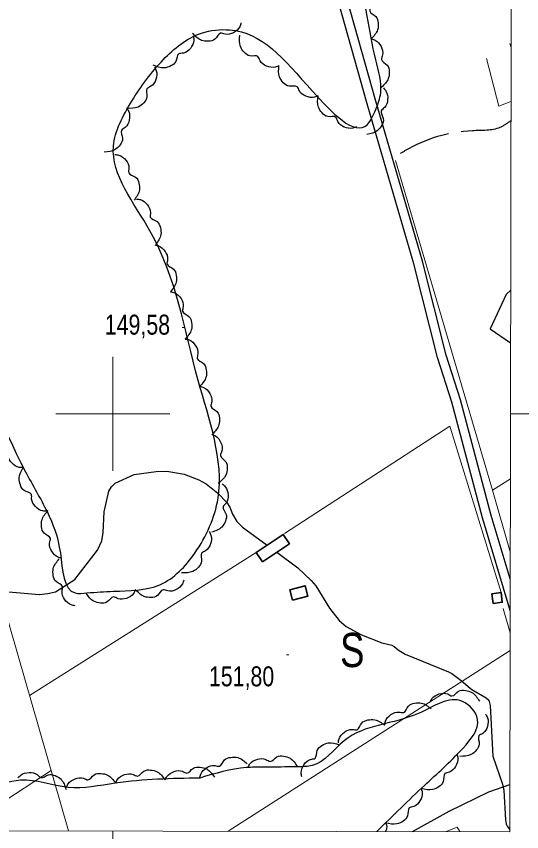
# Model space of a CAD drawing. Extents: x 483843 to 488449, y 4381269 to 4384483.
# Drawn here: x 487457.6 to 487679.3, y 4381816.7 to 4382174.3 of the extents above; entities that cross this region are included whole.
import ezdxf
from ezdxf.enums import TextEntityAlignment as Align

# ---------------------------------------------------------------- set-up
doc = ezdxf.new("R2010")
doc.units = 0
doc.header["$LTSCALE"] = 3.8
doc.linetypes.add('LONG_DASHED', pattern=[7.5, 6, -1.5])
for name, color, linetype, lineweight in [('1', 7, 'Continuous', 13), ('25', 7, 'LONG_DASHED', 25), ('27', 7, 'Continuous', 25), ('38', 7, 'Continuous', 25), ('47', 7, 'Continuous', 35), ('51', 7, 'Continuous', 13), ('7', 7, 'Continuous', 13), ('8', 7, 'Continuous', 25)]:
    doc.layers.add(name, color=color, linetype=linetype, lineweight=lineweight)
doc.layers.add('31', color=7, linetype='Continuous')

msp = doc.modelspace()

# ---------------------------------------------------------------- linework, layer by layer
at = {"layer": '1'}
for p, q in [((487500, 4382025), (487500, 4381975)), ((487475, 4382000), (487525, 4382000)), ((487674.41, 4382000), (487744.45, 4382000)), ((487500, 4381817.04), (487500, 4381745.69))]:
    msp.add_line(p, q, dxfattribs=at)
msp.add_lwpolyline([(484100.5, 4384135.8), (487678, 4384129), (487674.1, 4381816.7), (484095.6, 4381823.6)], close=True, dxfattribs=at)
at = {"layer": '25'}
for points in [[(487674.5, 4382054.12), (487672.47, 4382052.25), (487665.51, 4382037.18), (487674.46, 4382031.09)], [(487631.49, 4381816.78), (487647.5, 4381825.67), (487664.88, 4381834.13), (487674.14, 4381837.47)]]:
    msp.add_lwpolyline(points, dxfattribs=at)
at = {"layer": '27'}
for points in [[(486286.37, 4382818.73), (486339.99, 4382829.8), (486391.37, 4382851.5), (486440.09, 4382863.84), (486483.65, 4382864.6), (486530.94, 4382876.91), (486556.13, 4382891.91), (486581.09, 4382903.76), (486654.31, 4382924.49), (486662.47, 4382925.04), (486711.17, 4382931.08), (486727.4, 4382937.04), (486766.91, 4382937.87), (486808.31, 4382909.18), (486821.81, 4382880.51), (486820.67, 4382841.64), (486812.49, 4382812.89), (486799.42, 4382770.69), (486791.78, 4382745.03), (486785, 4382714.29), (486784.58, 4382691.25), (486792.33, 4382675.66), (486812.73, 4382668.89), (486834.8, 4382649.92), (486842.09, 4382627.43), (486847.24, 4382607.13), (486841.07, 4382582.93), (486840.3, 4382544.36), (486820.33, 4382480.87), (486817.63, 4382459.06), (486815.97, 4382420.47), (486812.52, 4382387.85), (486799.99, 4382362.84), (486771.04, 4382337.85), (486733.51, 4382314.2), (486712.72, 4382296.59), (486687.38, 4382263.88), (486690.96, 4382229.15), (486713.22, 4382200.82), (486764.33, 4382192.43), (486778.5, 4382149.68), (486779.01, 4382117.89), (486787.15, 4382072.98), (486813.93, 4382065.66), (486857.54, 4382071.08), (486866.35, 4382080.34), (486893.23, 4382096.95), (486915.85, 4382116.25), (486928.06, 4382127.9), (486936.43, 4382157.7), (486928.1, 4382176.05), (486914.22, 4382205.24), (486902.98, 4382218.81), (486885.61, 4382249.79), (486879.29, 4382279.36), (486884.99, 4382315.26), (486888.52, 4382343.76), (486907.35, 4382375.88), (486922.54, 4382388.35), (486945.58, 4382366.33), (486954.28, 4382323.31), (486963.51, 4382283.6), (486982.52, 4382253.24), (487009.26, 4382225.98), (487037.6, 4382230.32), (487058.96, 4382252.37), (487069.68, 4382284.84), (487065.95, 4382338.17), (487054.24, 4382363.72), (487038.01, 4382386.56), (487027.59, 4382400.37), (487012.06, 4382422.24), (486991.9, 4382450.1), (486977.88, 4382471.56), (486976.21, 4382486.9), (486980.43, 4382521.64), (487024.88, 4382562.69), (487055.81, 4382565.06), (487106.74, 4382596.8), (487155.96, 4382614.11), (487207.74, 4382666.72), (487232.21, 4382676.6), (487267.31, 4382683.94), (487282.71, 4382693.48), (487294.56, 4382707.98), (487340.16, 4382736.84), (487389.67, 4382736.07), (487421.36, 4382716.33), (487454.29, 4382680.57), (487455.44, 4382629.06), (487501.37, 4382598.97)], [(487674.99, 4382327.12), (487600.73, 4382281.96), (487559.96, 4382263.02), (487543.94, 4382264.48), (487524.28, 4382275.4), (487514.82, 4382289.97), (487514.82, 4382303.08), (487510.45, 4382314.01), (487500.26, 4382321.29), (487492.98, 4382322.75), (487481.33, 4382316.2), (487455.84, 4382279.05), (487420.9, 4382255.74), (487361.2, 4382229.51), (487353.92, 4382233.16), (487333.53, 4382276.86), (487330.62, 4382282.69), (487326.25, 4382284.15), (487321.15, 4382280.5), (487262.18, 4382225.87), (487217.04, 4382194.55), (487186.46, 4382174.88), (487179.18, 4382164.69), (487185.01, 4382145.02), (487193.01, 4382101.31), (487202.48, 4382091.85), (487210.49, 4382084.56), (487220.68, 4382080.92), (487233.79, 4382087.47), (487262.91, 4382104.96), (487326.98, 4382145.75), (487337.9, 4382147.93), (487343, 4382145.02), (487345.91, 4382133.36), (487351.73, 4382112.24), (487364.11, 4382095.49), (487370.66, 4382086.75), (487375.76, 4382079.46), (487377.94, 4382072.18), (487375.76, 4382064.89), (487372.12, 4382058.34), (487375.03, 4382046.68), (487383.77, 4382031.39), (487391.05, 4382027.75), (487408.52, 4382034.3), (487418.71, 4382042.31), (487424.54, 4382039.4), (487429.63, 4382034.3), (487461.67, 4381974.57), (487471.13, 4381957.09), (487476.96, 4381938.88), (487483.51, 4381921.4), (487488.61, 4381921.4), (487500.26, 4381922.13), (487520.64, 4381925.04), (487535.93, 4381938.88), (487546.12, 4381962.92), (487537.39, 4382014.63), (487516.27, 4382080.19), (487500.26, 4382117.34), (487508.26, 4382137.01), (487522.1, 4382155.22), (487538.84, 4382166.87), (487551.22, 4382168.33), (487587.62, 4382141.38), (487611.65, 4382126.81), (487615.29, 4382133.36), (487617.47, 4382140.65), (487615.29, 4382155.22), (487605.83, 4382193.09), (487591.99, 4382228.79), (487597.09, 4382238.26), (487616.75, 4382255.01), (487651.69, 4382276.86), (487675.72, 4382292.16)], [(487607.84, 4382185.35), (487609.55, 4382184.86), (487612.24, 4382182.19), (487613.06, 4382178.59), (487612.69, 4382176.57), (487615.34, 4382174.2), (487616.38, 4382171.4), (487616.15, 4382168.39), (487613.28, 4382164.34)], [(487556.19, 4382171.36), (487555.64, 4382169.67), (487552.88, 4382167.07), (487549.25, 4382166.38), (487547.25, 4382166.83), (487544.78, 4382164.27), (487541.95, 4382163.34), (487538.94, 4382163.68), (487535, 4382166.69)], [(487572.85, 4382152.64), (487571.2, 4382151.98), (487567.44, 4382152.45), (487564.59, 4382154.8), (487563.66, 4382156.63), (487560.11, 4382156.89), (487557.58, 4382158.48), (487555.92, 4382161.01), (487555.72, 4382165.96)], [(487535.36, 4382165.44), (487535.51, 4382163.67), (487533.98, 4382160.2), (487530.91, 4382158.15), (487528.89, 4382157.78), (487527.62, 4382154.46), (487525.37, 4382152.5), (487522.47, 4382151.64), (487517.67, 4382152.87)], [(487613.42, 4382164.38), (487615.1, 4382163.8), (487617.65, 4382160.99), (487618.28, 4382157.36), (487617.8, 4382155.36), (487620.32, 4382152.85), (487621.21, 4382150), (487620.82, 4382147), (487617.75, 4382143.11)], [(487518.26, 4382151.96), (487519.03, 4382150.37), (487518.83, 4382146.58), (487516.69, 4382143.57), (487514.93, 4382142.51), (487514.93, 4382138.95), (487513.52, 4382136.32), (487511.12, 4382134.49), (487506.19, 4382133.93)], [(487590.1, 4382139.49), (487588.46, 4382138.82), (487584.69, 4382139.25), (487581.82, 4382141.57), (487580.87, 4382143.39), (487577.32, 4382143.61), (487574.77, 4382145.17), (487573.09, 4382147.69), (487572.84, 4382152.64)], [(487618.64, 4382142.84), (487619.79, 4382141.48), (487620.53, 4382137.76), (487619.19, 4382134.32), (487617.75, 4382132.85), (487618.62, 4382129.4), (487617.91, 4382126.5), (487616.03, 4382124.14), (487611.39, 4382122.38)], [(487606.94, 4382125.82), (487605.28, 4382125.19), (487601.52, 4382125.72), (487598.72, 4382128.12), (487597.82, 4382129.97), (487594.28, 4382130.29), (487591.77, 4382131.92), (487590.16, 4382134.48), (487590.05, 4382139.44)], [(487505.98, 4382134.06), (487506.94, 4382132.57), (487507.21, 4382128.78), (487505.46, 4382125.53), (487503.84, 4382124.26), (487504.27, 4382120.73), (487503.21, 4382117.94), (487501.05, 4382115.83), (487496.23, 4382114.67)], [(487500.86, 4382113.64), (487502.62, 4382113.42), (487505.69, 4382111.19), (487507.04, 4382107.76), (487506.98, 4382105.7), (487509.95, 4382103.76), (487511.4, 4382101.15), (487511.63, 4382098.14), (487509.41, 4382093.7)], [(487510.31, 4382094.13), (487512.07, 4382093.91), (487515.14, 4382091.67), (487516.49, 4382088.23), (487516.42, 4382086.18), (487519.39, 4382084.23), (487520.83, 4382081.62), (487521.06, 4382078.61), (487518.83, 4382074.17)], [(487518.34, 4382074), (487520.08, 4382073.63), (487522.95, 4382071.15), (487524.01, 4382067.62), (487523.78, 4382065.58), (487526.59, 4382063.4), (487527.81, 4382060.67), (487527.79, 4382057.65), (487525.21, 4382053.41)], [(487525.34, 4382053.47), (487527.07, 4382053.06), (487529.89, 4382050.52), (487530.87, 4382046.97), (487530.59, 4382044.93), (487533.35, 4382042.69), (487534.52, 4382039.94), (487534.43, 4382036.92), (487531.76, 4382032.74)], [(487531.77, 4382032.75), (487533.49, 4382032.35), (487536.31, 4382029.81), (487537.3, 4382026.25), (487537.02, 4382024.22), (487539.78, 4382021.97), (487540.95, 4382019.22), (487540.86, 4382016.2), (487538.19, 4382012.02)], [(487538.09, 4382012.01), (487539.8, 4382011.53), (487542.52, 4382008.88), (487543.37, 4382005.29), (487543.01, 4382003.27), (487545.67, 4382000.92), (487546.73, 4381998.13), (487546.52, 4381995.11), (487543.69, 4381991.04)], [(487460.71, 4381976.37), (487458.93, 4381976.44), (487455.68, 4381978.4), (487454.04, 4381981.7), (487453.93, 4381983.75), (487450.79, 4381985.43), (487449.12, 4381987.91), (487448.64, 4381990.89), (487450.47, 4381995.5)], [(487543.44, 4381990.97), (487545.07, 4381990.27), (487547.42, 4381987.29), (487547.78, 4381983.62), (487547.16, 4381981.66), (487549.5, 4381978.98), (487550.18, 4381976.07), (487549.57, 4381973.11), (487546.23, 4381969.45)], [(487471.07, 4381957.32), (487469.3, 4381957.37), (487466.04, 4381959.31), (487464.37, 4381962.6), (487464.24, 4381964.65), (487461.09, 4381966.31), (487459.41, 4381968.77), (487458.9, 4381971.75), (487460.7, 4381976.37)], [(487548, 4381969.21), (487549.3, 4381968), (487550.51, 4381964.41), (487549.63, 4381960.82), (487548.38, 4381959.19), (487549.68, 4381955.88), (487549.35, 4381952.91), (487547.79, 4381950.33), (487543.41, 4381948)], [(487477.67, 4381936.68), (487475.95, 4381937.11), (487473.18, 4381939.7), (487472.26, 4381943.28), (487472.57, 4381945.3), (487469.85, 4381947.6), (487468.73, 4381950.36), (487468.88, 4381953.38), (487471.62, 4381957.52)], [(487542.26, 4381948.3), (487543.03, 4381946.7), (487542.82, 4381942.91), (487540.67, 4381939.91), (487538.91, 4381938.85), (487538.89, 4381935.29), (487537.49, 4381932.66), (487535.08, 4381930.84), (487530.15, 4381930.29)], [(487483.44, 4381915.83), (487481.7, 4381916.18), (487478.81, 4381918.64), (487477.71, 4381922.16), (487477.93, 4381924.21), (487475.11, 4381926.37), (487473.86, 4381929.08), (487473.86, 4381932.1), (487476.41, 4381936.36)], [(487531.14, 4381927.07), (487530.55, 4381925.4), (487527.72, 4381922.87), (487524.07, 4381922.28), (487522.08, 4381922.78), (487519.55, 4381920.29), (487516.69, 4381919.43), (487513.7, 4381919.85), (487509.83, 4381922.96)], [(487509.86, 4381922.76), (487509.06, 4381921.18), (487505.93, 4381919.03), (487502.25, 4381918.89), (487500.33, 4381919.64), (487497.51, 4381917.48), (487494.56, 4381916.98), (487491.65, 4381917.77), (487488.2, 4381921.34)], [(487615.72, 4381816.81), (487636.69, 4381836.99), (487653.6, 4381853.4), (487660.01, 4381865.98), (487653.32, 4381873.87), (487634.38, 4381868.74), (487601.4, 4381856.58), (487587.46, 4381845.71), (487581.32, 4381845.21), (487578.69, 4381845.16), (487565.72, 4381845.03), (487558.6, 4381844.81), (487538.14, 4381840.26)], [(487639.11, 4381873.57), (487639.97, 4381875.12), (487643.19, 4381877.13), (487646.88, 4381877.1), (487648.76, 4381876.27), (487651.68, 4381878.3), (487654.64, 4381878.66), (487657.52, 4381877.74), (487660.8, 4381874.02)], [(487619.2, 4381863.4), (487619.54, 4381865.14), (487621.97, 4381868.05), (487625.49, 4381869.17), (487627.53, 4381868.97), (487629.67, 4381871.81), (487632.37, 4381873.08), (487635.4, 4381873.11), (487639.67, 4381870.59)], [(487598.94, 4381855.63), (487599.23, 4381857.38), (487601.57, 4381860.37), (487605.05, 4381861.59), (487607.1, 4381861.45), (487609.15, 4381864.35), (487611.82, 4381865.7), (487614.84, 4381865.82), (487619.19, 4381863.43)], [(487663.5, 4381868.28), (487664.33, 4381866.71), (487664.29, 4381862.92), (487662.27, 4381859.83), (487660.56, 4381858.69), (487660.7, 4381855.14), (487659.41, 4381852.45), (487657.08, 4381850.52), (487652.18, 4381849.76)], [(487582.92, 4381840.74), (487582.61, 4381842.49), (487583.82, 4381846.08), (487586.7, 4381848.4), (487588.67, 4381848.95), (487589.64, 4381852.37), (487591.7, 4381854.53), (487594.51, 4381855.65), (487599.4, 4381854.86)], [(487538.14, 4381840.26), (487538.56, 4381841.98), (487541.12, 4381844.78), (487544.69, 4381845.74), (487546.72, 4381845.44), (487548.99, 4381848.18), (487551.75, 4381849.32), (487554.77, 4381849.21), (487558.92, 4381846.5)], [(487559.27, 4381844.97), (487560.15, 4381846.51), (487563.4, 4381848.48), (487567.09, 4381848.4), (487568.95, 4381847.55), (487571.9, 4381849.55), (487574.86, 4381849.88), (487577.73, 4381848.93), (487580.97, 4381845.17)], [(487650.91, 4381850.73), (487651.32, 4381849.01), (487650.33, 4381845.35), (487647.6, 4381842.86), (487645.66, 4381842.2), (487644.9, 4381838.72), (487642.97, 4381836.44), (487640.23, 4381835.16), (487635.3, 4381835.66)], [(487501.24, 4381837.99), (487502.04, 4381839.58), (487505.17, 4381841.73), (487508.86, 4381841.86), (487510.77, 4381841.12), (487513.59, 4381843.28), (487516.54, 4381843.77), (487519.45, 4381842.99), (487522.9, 4381839.41)], [(487522.9, 4381839.39), (487523.71, 4381840.97), (487526.86, 4381843.09), (487530.55, 4381843.19), (487532.45, 4381842.43), (487535.3, 4381844.57), (487538.24, 4381845.03), (487541.15, 4381844.22), (487544.56, 4381840.62)], [(487538.14, 4381840.26), (487501.06, 4381837.98), (487480.33, 4381836.13), (487459.41, 4381839.29), (487445.42, 4381833.82), (487434.09, 4381817.16)], [(487458.38, 4381840.28), (487459.61, 4381841.56), (487463.23, 4381842.69), (487466.79, 4381841.73), (487468.4, 4381840.46), (487471.74, 4381841.69), (487474.7, 4381841.3), (487477.25, 4381839.69), (487479.49, 4381835.26)], [(487479.63, 4381836.07), (487480.39, 4381837.67), (487483.45, 4381839.9), (487487.14, 4381840.13), (487489.07, 4381839.44), (487491.84, 4381841.67), (487494.77, 4381842.24), (487497.7, 4381841.53), (487501.24, 4381838.05)], [(487635.3, 4381835.66), (487635.72, 4381833.93), (487634.71, 4381830.27), (487631.98, 4381827.79), (487630.04, 4381827.13), (487629.27, 4381823.66), (487627.34, 4381821.38), (487624.6, 4381820.1), (487619.66, 4381820.61)], [(487619.75, 4381820.52), (487620.14, 4381818.79), (487619.57, 4381816.81)]]:
    msp.add_spline(points, degree=3, dxfattribs=at)
at = {"layer": '38'}
for p, q in [((487674.26, 4381913.65), (487674.26, 4381913.66)), ((487674.26, 4381913.64), (487674.26, 4381913.65)), ((487674.26, 4381913.63), (487674.26, 4381913.64)), ((487674.26, 4381913.62), (487674.26, 4381913.63)), ((487674.26, 4381913.61), (487674.26, 4381913.62)), ((487674.26, 4381913.6), (487674.26, 4381913.61)), ((487674.26, 4381913.59), (487674.26, 4381913.6)), ((487674.26, 4381913.58), (487674.26, 4381913.59))]:
    msp.add_line(p, q, dxfattribs=at)
for points in [[(487674.29, 4381927.56), (487665.92, 4381955.36), (487652.48, 4382006.12), (487646.22, 4382025.7), (487635.78, 4382066.83), (487615.39, 4382137.04), (487593.44, 4382215.01), (487575.19, 4382279.67), (487561.71, 4382320.42)], [(487674.26, 4381913.66), (487662.14, 4381954.3), (487648.71, 4382005.02), (487642.45, 4382024.62), (487631.99, 4382065.8), (487611.62, 4382135.96), (487589.66, 4382213.95), (487571.44, 4382278.52), (487557.99, 4382319.19)]]:
    msp.add_lwpolyline(points, dxfattribs=at)
at = {"layer": '38', "linetype": 'LONG_DASHED'}
msp.add_spline([(487674.63, 4382128.48), (487669.81, 4382125.55), (487657.77, 4382124.09), (487628.25, 4382115.38), (487623.95, 4382112.74)], degree=3, dxfattribs=at)
at = {"layer": '47'}
for points in [[(487562.93, 4381939.1), (487574.75, 4381947.05), (487577.47, 4381943.01), (487565.65, 4381935.06)], [(487578.82, 4381918.21), (487585.59, 4381920.01), (487584.38, 4381924.55), (487577.61, 4381922.75)], [(487670.33, 4381921.55), (487670.83, 4381917.3), (487666.75, 4381916.82), (487666.25, 4381921.07)]]:
    msp.add_lwpolyline(points, close=True, dxfattribs=at)
at = {"layer": '51'}
for p, q in [((487674.14, 4382162.39), (487674.68, 4382160.6)), ((487674.31, 4381939.48), (487666.46, 4381966.54)), ((487463.45, 4381876.42), (487562.93, 4381939.1)), ((487671.15, 4381914.59), (487674.25, 4381903.9)), ((487550.55, 4381816.94), (487674.23, 4381896.17)), ((487432.45, 4381817.17), (487472.9, 4381843.52))]:
    msp.add_line(p, q, dxfattribs=at)
for points in [[(487381.49, 4382167.08), (487455.1, 4381905.5), (487480.5, 4381817.07)], [(487674.64, 4382136.96), (487669.32, 4382134.84), (487663.86, 4382155.8)], [(487623.92, 4382111.01), (487666.46, 4381966.54), (487674.36, 4381971.52)], [(487575.35, 4381947.46), (487647.88, 4381994.51), (487670.33, 4381921.55)], [(487646.23, 4381816.75), (487651.02, 4381818.69), (487652.23, 4381816.74)]]:
    msp.add_lwpolyline(points, dxfattribs=at)
at = {"layer": '7'}
for p, q in [((487530.44, 4382037.82), (487531.44, 4382037.82)), ((487576.19, 4381894.32), (487577.19, 4381894.32))]:
    msp.add_line(p, q, dxfattribs=at)
at = {"layer": '8'}
for points in [[(487431.03, 4381923.9), (487467.62, 4381920.77), (487471.49, 4381921.18), (487474.9, 4381921.92), (487483.32, 4381927.35), (487493.23, 4381940.2), (487495.13, 4381944.28), (487495.77, 4381947.92), (487496.2, 4381956.98), (487498.18, 4381965.98), (487499.45, 4381967.89), (487501.03, 4381969.54), (487509.31, 4381973.37), (487518.95, 4381974.71), (487523.71, 4381974.75), (487531.26, 4381973.54), (487537.72, 4381971.02), (487540.94, 4381969.21), (487546.11, 4381965.19), (487549.99, 4381961.04), (487551.37, 4381959.04), (487552.5, 4381955.97), (487554.4, 4381952.67), (487556.87, 4381950.33), (487567.71, 4381942.31)], [(487571.86, 4381939.24), (487581.11, 4381932.4), (487586.98, 4381926.87), (487589.02, 4381924.56), (487595.08, 4381914.69), (487599.29, 4381909.31), (487602.33, 4381906.77), (487609.09, 4381903), (487618.02, 4381899.47), (487622.39, 4381898.47), (487623.33, 4381897.97), (487625.12, 4381896.51), (487628.24, 4381894.51), (487647.22, 4381886.88), (487648.73, 4381886.06), (487652.84, 4381883.03), (487656.69, 4381879.65), (487657.51, 4381879.06), (487663.82, 4381875.42), (487664.89, 4381874.44), (487665.44, 4381872.11), (487666.71, 4381849.79), (487670.92, 4381837.6), (487671.43, 4381834.74), (487672.18, 4381821.91), (487672.49, 4381820.2), (487672.87, 4381819.49), (487672.94, 4381819.28), (487673.07, 4381819.01), (487674.1, 4381817.48)]]:
    msp.add_lwpolyline(points, dxfattribs=at)

# ---------------------------------------------------------------- texts
at = {"layer": '31', "width": 0.8}
msp.add_text('S', height=15, dxfattribs=at).set_placement((487605.01, 4381888.9), align=Align.CENTER)
at = {"layer": '7', "width": 0.8}
for s, p in [('149,58', (487496.46, 4382034.69)), ('151,80', (487542.14, 4381880.47))]:
    msp.add_text(s, height=8.75, dxfattribs=at).set_placement(p)

doc.saveas('drawing.dxf')
